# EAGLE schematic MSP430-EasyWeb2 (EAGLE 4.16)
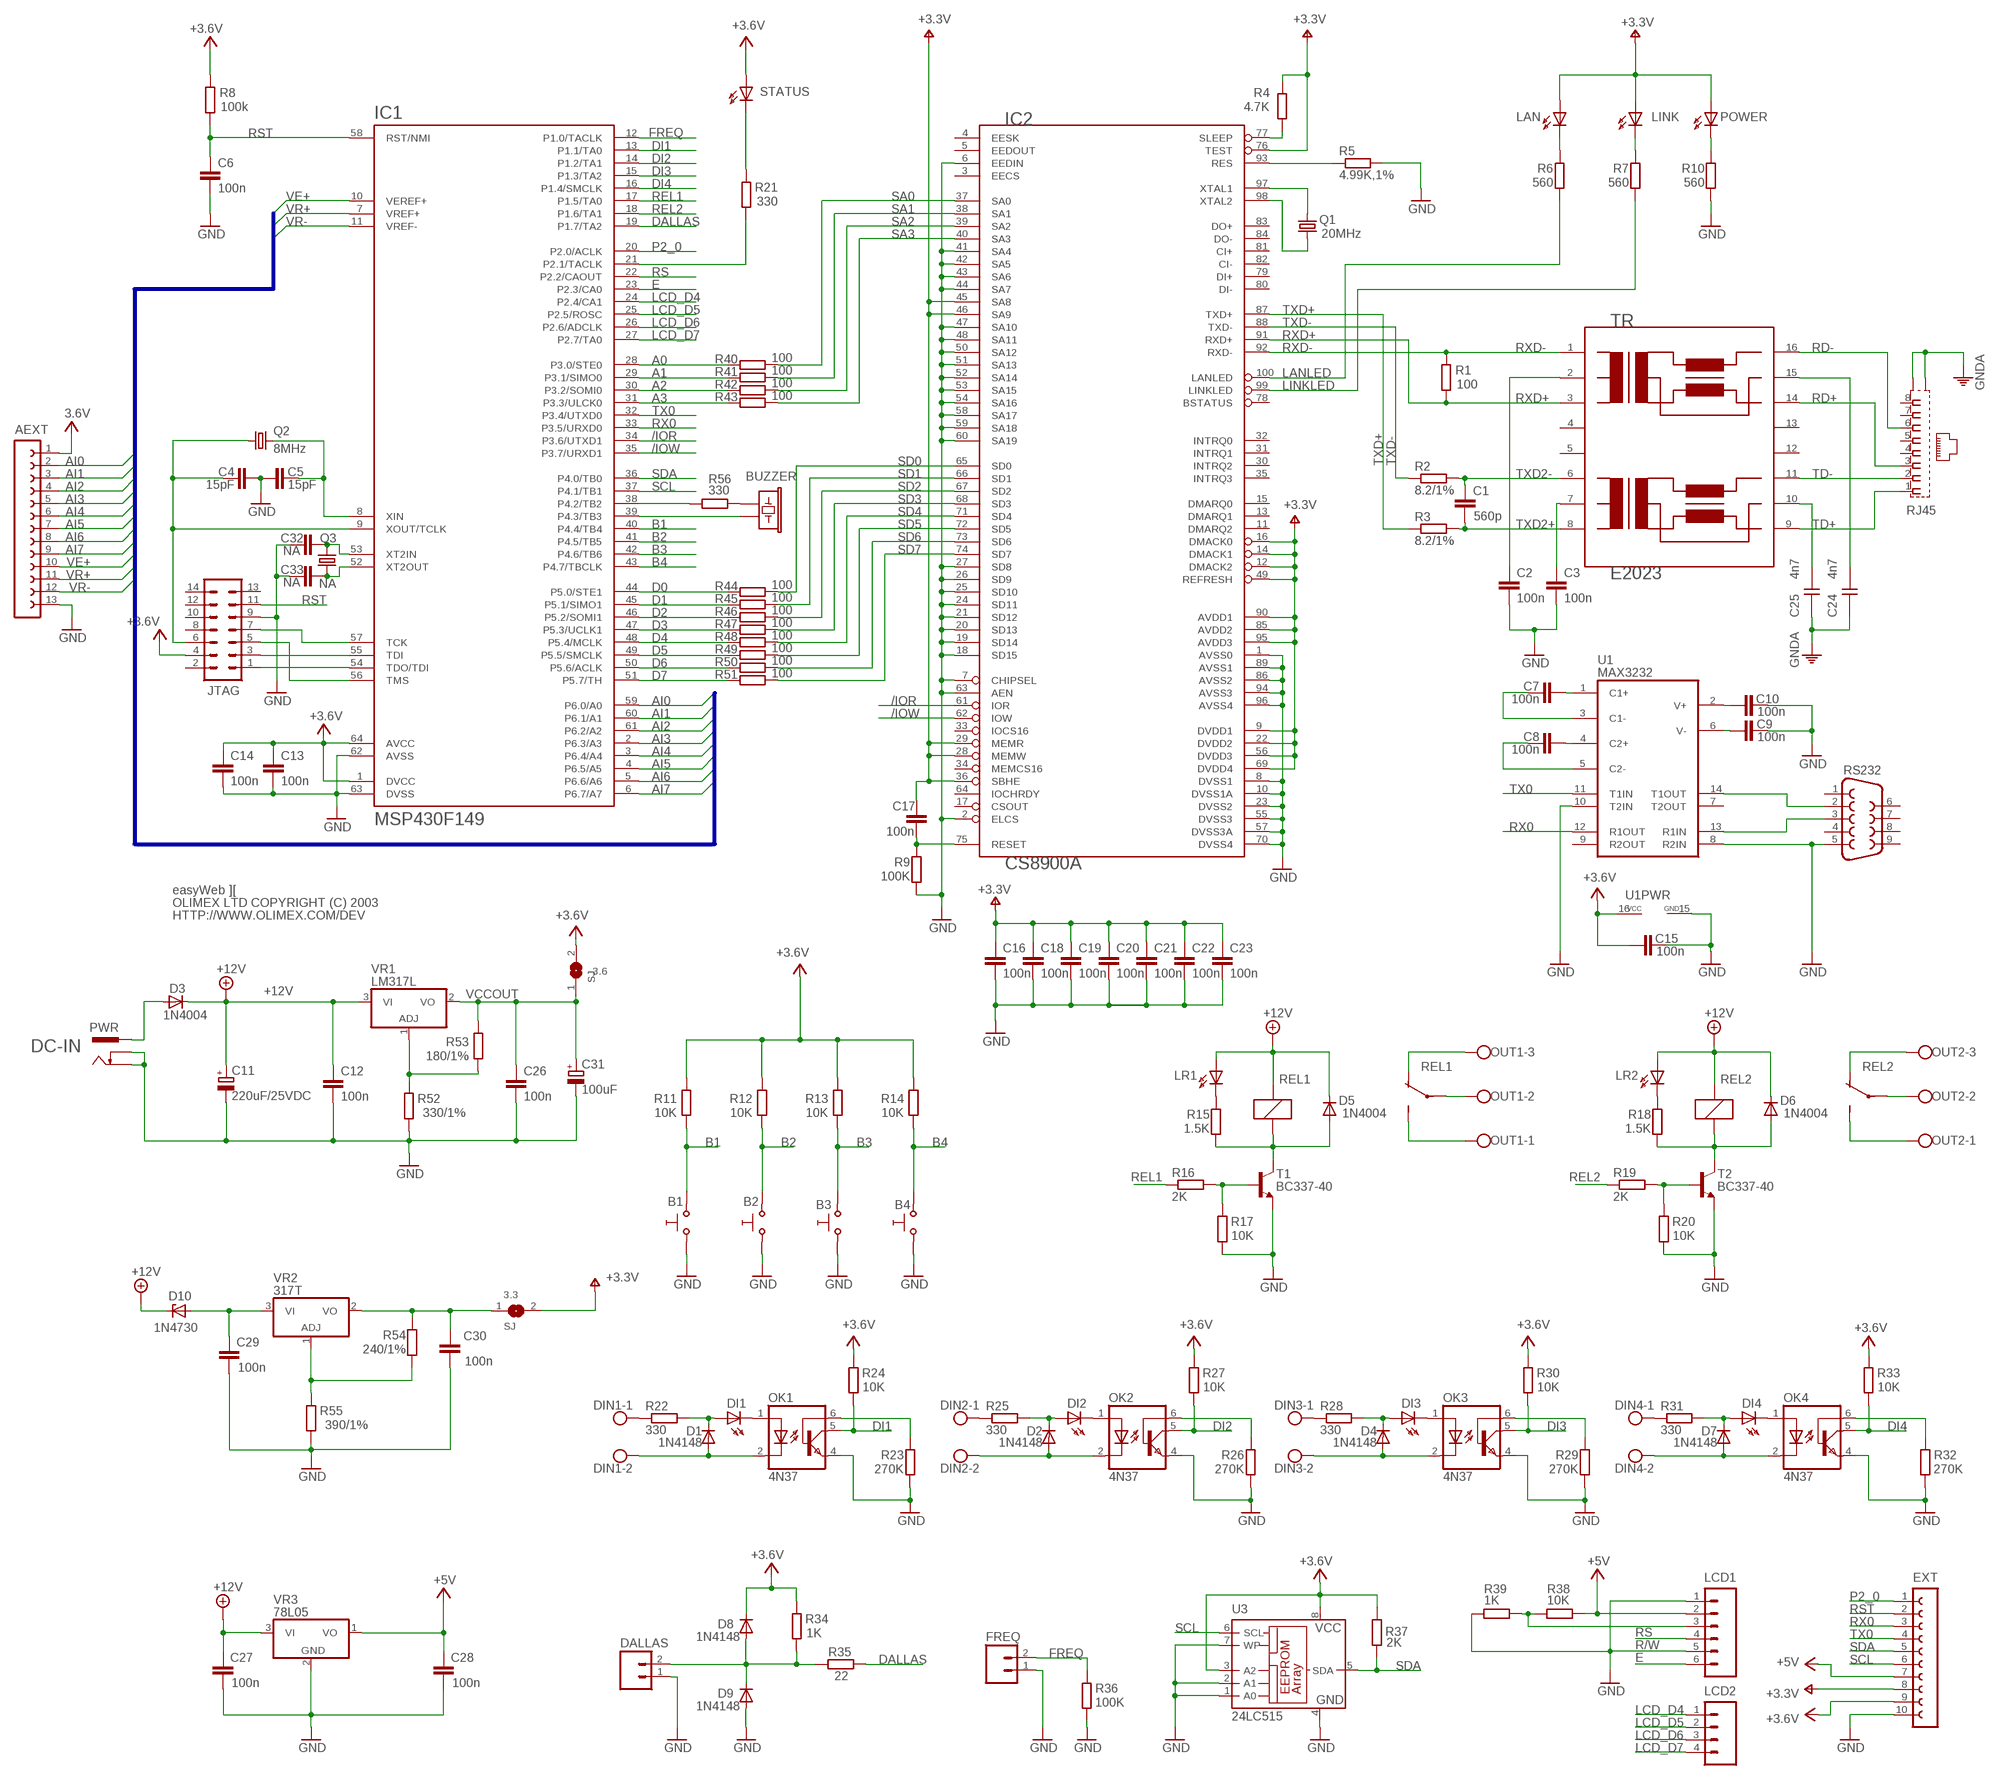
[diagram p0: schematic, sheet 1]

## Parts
3.3  SJ  [SJ]
3.6  SJ  [SJ]
AEXT  FE13-1  [FE13]
B1  SW-TAKT5  [SW_TAKT12X12]
B2  SW-TAKT5  [SW_TAKT12X12]
B3  SW-TAKT5  [SW_TAKT12X12]
B4  SW-TAKT5  [SW_TAKT12X12]
BUZZER  BUZ1  [BUZ1]
C1  560p  C-EUC0805  [C0805]
C2  100n  C-EUC0805  [C0805]
C3  100n  C-EUC0805  [C0805]
C4  15pF  C-EUC0805  [C0805]
C5  15pF  C-EUC0805  [C0805]
C6  100n  C-EUC0805  [C0805]
C7  100n  C-EUC0805  [C0805]
C8  100n  C-EUC0805  [C0805]
C9  100n  C-EUC0805  [C0805]
C10  100n  C-EUC0805  [C0805]
C11  220uF/25VDC  CPOL-EUE3.5-8  [E3,5-8]
C12  100n  C-EUC0805  [C0805]
C13  100n  C-EUC0805  [C0805]
C14  100n  C-EUC0805  [C0805]
C15  100n  C-EUC0805  [C0805]
C16  100n  C-EUC0805  [C0805]
C17  100n  C-EUC0805  [C0805]
C18  100n  C-EUC0805  [C0805]
C19  100n  C-EUC0805  [C0805]
C20  100n  C-EUC0805  [C0805]
C21  100n  C-EUC0805  [C0805]
C22  100n  C-EUC0805  [C0805]
C23  100n  C-EUC0805  [C0805]
C24  4n7  CAPNP-2,5@2  [C-5]
C25  4n7  CAPNP-2,5@2  [C-5]
C26  100n  C-EUC0805  [C0805]
C27  100n  C-EUC0805  [C0805]
C28  100n  C-EUC0805  [C0805]
C29  100n  C-EUC0805  [C0805]
C30  100n  C-EUC0805  [C0805]
C31  100uF  CPOL-EUE2.5-6  [E2,5-6]
C32  NA  C-EUC0805  [C0805]
C33  NA  C-EUC0805  [C0805]
D1  1N4148  DIODE-SOD80C  [SOD80C]
D2  1N4148  DIODE-SOD80C  [SOD80C]
D3  1N4004  DIODE-D-7.5  [D-7.5]
D4  1N4148  DIODE-SOD80C  [SOD80C]
D5  1N4004  D1N4004-7.62MM  [DO41-10]
D6  1N4004  D1N4004-7.62MM  [DO41-10]
D7  1N4148  DIODE-SOD80C  [SOD80C]
D8  1N4148  D1N4148-7.62MM  [DO35-10]
D9  1N4148  D1N4148-7.62MM  [DO35-10]
D10  1N4730  Z  [1N4742]
DALLAS  CON2PV2-2.54MM  [CON2.54MM-2-0]
DI1  LED5.0MM  [LED-5.0MM]
DI2  LED5.0MM  [LED-5.0MM]
DI3  LED5.0MM  [LED-5.0MM]
DI4  LED5.0MM  [LED-5.0MM]
DIN1  W237-102  [W237-102]
DIN2  W237-102  [W237-102]
DIN3  W237-102  [W237-102]
DIN4  W237-102  [W237-102]
EXT  FE10-1  [FE10]
FREQ  CON2PV2-2.54MM  [CON2.54MM-2-0]
IC1  MSP430F149  430F149  [S-PQFP-G]
IC2  CS8900A  [100LTQFP]
JTAG  ML14  [ML14]
LAN  LED5.0MM  [LED-5.0MM]
LCD1  HEAD6  [HEADER2.54-6-0]
LCD2  HEAD4  [HEADER2.54-4-0]
LINK  LED5.0MM  [LED-5.0MM]
LR1  LED5.0MM  [LED-5.0MM]
LR2  LED5.0MM  [LED-5.0MM]
OK1  4N37  [DIL06]
OK2  4N37  [DIL06]
OK3  4N37  [DIL06]
OK4  4N37  [DIL06]
OUT1  W237-103  [W237-103]
OUT2  W237-103  [W237-103]
POWER  LED5.0MM  [LED-5.0MM]
PWR  PWR-JAK2  [PWR-JACK2]
Q1  20MHz  HC49/S  [HC49/S]
Q2  8MHz  HC49/S  [HC49/S]
Q3  NA  HC49/S  [HC49/S]
R1  100  R-EU_R0805  [R0805]
R2  8.2/1%  R-EU_R0805  [R0805]
R3  8.2/1%  R-EU_R0805  [R0805]
R4  4.7K  R-EU_R0805  [R0805]
R5  4.99K,1%  R-EU_R0805  [R0805]
R6  560  R-EU_R0805  [R0805]
R7  560  R-EU_R0805  [R0805]
R8  100k  R-EU_R0805  [R0805]
R9  100K  R-EU_R0805  [R0805]
R10  560  R-EU_R0805  [R0805]
R11  10K  R-EU_R0805  [R0805]
R12  10K  R-EU_R0805  [R0805]
R13  10K  R-EU_R0805  [R0805]
R14  10K  R-EU_R0805  [R0805]
R15  1.5K  R-EU_R0805  [R0805]
R16  2K  R-EU_R0805  [R0805]
R17  10K  R-EU_R0805  [R0805]
R18  1.5K  R-EU_R0805  [R0805]
R19  2K  R-EU_R0805  [R0805]
R20  10K  R-EU_R0805  [R0805]
R21  330  R-EU_R0805  [R0805]
R22  330  R-EU_R0805  [R0805]
R23  270K  R-EU_R0805  [R0805]
R24  10K  R-EU_R0805  [R0805]
R25  330  R-EU_R0805  [R0805]
R26  270K  R-EU_R0805  [R0805]
R27  10K  R-EU_R0805  [R0805]
R28  330  R-EU_R0805  [R0805]
R29  270K  R-EU_R0805  [R0805]
R30  10K  R-EU_R0805  [R0805]
R31  330  R-EU_R0805  [R0805]
R32  270K  R-EU_R0805  [R0805]
R33  10K  R-EU_R0805  [R0805]
R34  1K  R-EU_R0805  [R0805]
R35  22  R-EU_R0805  [R0805]
R36  100K  R-EU_R0805  [R0805]
R37  2K  R-EU_R0805  [R0805]
R38  10K  R-EU_R0805  [R0805]
R39  1K  R-EU_R0805  [R0805]
R40  100  R-EU_R0805  [R0805]
R41  100  R-EU_R0805  [R0805]
R42  100  R-EU_R0805  [R0805]
R43  100  R-EU_R0805  [R0805]
R44  100  R-EU_R0805  [R0805]
R45  100  R-EU_R0805  [R0805]
R46  100  R-EU_R0805  [R0805]
R47  100  R-EU_R0805  [R0805]
R48  100  R-EU_R0805  [R0805]
R49  100  R-EU_R0805  [R0805]
R50  100  R-EU_R0805  [R0805]
R51  100  R-EU_R0805  [R0805]
R52  330/1%  R-EU_R0805  [R0805]
R53  180/1%  R-EU_R0805  [R0805]
R54  240/1%  R-EU_R0805  [R0805]
R55  390/1%  R-EU_R0805  [R0805]
R56  330  R-EU_R0805  [R0805]
REL1  RELAYH200F  [H200-FAT]
REL2  RELAYH200F  [H200-FAT]
RJ45  555153-1  [555153-1]
RS232  F09HP  [F09HP]
STATUS  LED5.0MM  [LED-5.0MM]
T1  BC337-40  NPNBC337-  [TO92-M]
T2  BC337-40  NPNBC337-  [TO92-M]
TR  E2023  [SO-16L]
U1  MAX3232  [SO16-150MILS]
U3  24LC515  24LCXX  [SO-08MN]
VR1  LM317L  LM317LZ  [TO92]
VR2  317T  [TO220H]
VR3  78L05  78L05Z  [TO92]

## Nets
317_+3.3V: 3.3.1 C30.2 R54.2 VR2.2(VO)
+3.3V [PWR]: 3.3.2 C16.1 C17.1 C18.1 C19.1 C20.1 C21.1 C22.1 C23.1 EXT.8 IC2.9(DVDD1) IC2.12(DMACK2) IC2.14(DMACK1) IC2.16(DMACK0) IC2.22(DVDD2) IC2.28(MEMW) IC2.29(MEMR) IC2.36(SBHE) IC2.45(SA8) IC2.46(SA9) IC2.49(REFRESH) IC2.56(DVDD3) IC2.69(DVDD4) IC2.76(TEST) IC2.85(AVDD2) IC2.90(AVDD1) IC2.95(AVDD3) LAN.A LINK.A POWER.A R4.2
+3.6V [PWR]: 3.6.2 AEXT.1 C13.1 C14.1 C15.1 D8.K EXT.9 IC1.1(DVCC) IC1.64(AVCC) JTAG.4 R8.2 R11.2 R12.2 R13.2 R14.2 R24.2 R27.2 R30.2 R33.2 R34.2 R37.2 STATUS.A U1.16(VCC) U3.3(A2) U3.8(VCC) ; supply symbol labelled 3.6V
+5V: C28.2 EXT.7 LCD1.2 R38.2 VR3.1(VO)
+12V [PWR]: C11.+ C12.1 C27.2 D3.C D5.K D6.K D10.K LR1.A LR2.A REL1.1 REL2.1 VR1.3(VI) VR3.3(VI)
/IOR: IC1.34(P3.6/UTXD1) IC2.61(IOR)
/IOW: IC1.35(P3.7/URXD1) IC2.62(IOW)
A0: IC1.28(P3.0/STE0) R40.1
A1: IC1.29(P3.1/SIMO0) R41.1
A2: IC1.30(P3.2/SOMI0) R42.1
A3: IC1.31(P3.3/ULCK0) R43.1
AI0: AEXT.2 IC1.59(P6.0/A0)
AI1: AEXT.3 IC1.60(P6.1/A1)
AI2: AEXT.4 IC1.61(P6.2/A2)
AI3: AEXT.5 IC1.2(P6.3/A3)
AI4: AEXT.6 IC1.3(P6.4/A4)
AI5: AEXT.7 IC1.4(P6.5/A5)
AI6: AEXT.8 IC1.5(P6.6/A6)
AI7: AEXT.9 IC1.6(P6.7/A7)
B1: B1.P$2 IC1.40(P4.4/TB4) R11.1
B2: B2.P$2 IC1.41(P4.5/TB5) R12.1
B3: B3.P$2 IC1.42(P4.6/TB6) R13.1
B4: B4.P$2 IC1.43(P4.7/TBCLK) R14.1
D0: IC1.44(P5.0/STE1) R44.1
D1: IC1.45(P5.1/SIMO1) R45.1
D2: IC1.46(P5.2/SOMI1) R46.1
D3: IC1.47(P5.3/UCLK1) R47.1
D4: IC1.48(P5.4/MCLK) R48.1
D5: IC1.49(P5.5/SMCLK) R49.1
D6: IC1.50(P5.6/ACLK) R50.1
D7: IC1.51(P5.7/TH) R51.1
DALLAS: IC1.19(P1.7/TA2) R35.2
DI1: IC1.13(P1.1/TA0) OK1.5(COL) R24.1
DI2: IC1.14(P1.2/TA1) OK2.5(COL) R27.1
DI3: IC1.15(P1.3/TA2) OK3.5(COL) R30.1
DI4: IC1.16(P1.4/SMCLK) OK4.5(COL) R33.1
E: IC1.23(P2.3/CA0) LCD1.6
ETH_RES: C17.2 IC2.75(RESET) R9.2
FREQ: FREQ.2 IC1.12(P1.0/TACLK) R36.2
GND [PWR]: AEXT.13 B1.P$1 B2.P$1 B3.P$1 B4.P$1 C2.2 C3.2 C4.2 C5.1 C6.2 C9.2 C10.2 C11.- C12.2 C13.2 C14.2 C15.2 C16.2 C18.2 C19.2 C20.2 C21.2 C22.2 C23.2 C26.2 C27.1 C28.1 C29.1 C30.1 C31.- C32.1 C33.1 D9.A DALLAS.1 EXT.10 FREQ.1 IC1.62(AVSS) IC1.63(DVSS) IC2.1(AVSS0) IC2.2(ELCS) IC2.6(EEDIN) IC2.7(CHIPSEL) IC2.8(DVSS1) IC2.10(DVSS1A) IC2.18(SD15) IC2.19(SD14) IC2.20(SD13) IC2.21(SD12) IC2.23(DVSS2) IC2.24(SD11) IC2.25(SD10) IC2.26(SD9) IC2.27(SD8) IC2.41(SA4) IC2.42(SA5) IC2.43(SA6) IC2.44(SA7) IC2.47(SA10) IC2.48(SA11) IC2.50(SA12) IC2.51(SA13) IC2.52(SA14) IC2.53(SA15) IC2.54(SA16) IC2.55(DVSS3) IC2.57(DVSS3A) IC2.58(SA17) IC2.59(SA18) IC2.60(SA19) IC2.63(AEN) IC2.70(DVSS4) IC2.86(AVSS2) IC2.89(AVSS1) IC2.94(AVSS3) IC2.96(AVSS4) JTAG.9 LCD1.1 LCD1.5 OK1.4(EMI) OK2.4(EMI) OK3.4(EMI) OK4.4(EMI) PWR.- PWR.-- R5.2 R9.1 R10.1 R17.1 R20.1 R23.1 R26.1 R29.1 R32.1 R36.1 R39.1 R52.1 R55.1 RS232.5 T1.1(E) T2.1(E) U1.8(R2IN) U1.10(T2IN) U1.15(GND) U3.1(A0) U3.2(A1) U3.4(GND) U3.7(WP) VR3.2(GND)
GNDA: C24.1 C25.1 RJ45.G1(S1) RJ45.G2(S2)
LANLED: IC2.100(LANLED) R6.1
LCD_D4: IC1.24(P2.4/CA1) LCD2.1
LCD_D5: IC1.25(P2.5/ROSC) LCD2.2
LCD_D6: IC1.26(P2.6/ADCLK) LCD2.3
LCD_D7: IC1.27(P2.7/TA0) LCD2.4
LINKLED: IC2.99(LINKLED) R7.1
N$1: POWER.K(C) R10.2
N$2: LINK.K(C) R7.2
N$3: LAN.K(C) R6.2
N$4: D3.A PWR.+
N$5: C7.2 U1.1(C1+)
N$6: C8.2 U1.4(C2+)
N$7: C2.1 TR.2
N$8: C3.1 TR.7
N$9: IC2.97(XTAL1) Q1.2
N$10: IC2.77(SLEEP) R4.1
N$11: IC2.93(RES) R5.1
N$12: IC2.98(XTAL2) Q1.1
N$13: C29.2 D10.A VR2.3(VI)
N$14: C9.1 U1.6(V-)
N$15: RS232.3 U1.13(R1IN)
N$16: C10.1 U1.2(V+)
N$17: D5.A R15.1 REL1.2 T1.3(C)
N$18: R16.2 R17.2 T1.2(B)
N$19: R21.2 STATUS.K(C)
N$20: DIN1.1 R22.1
N$21: C7.1 U1.3(C1-)
N$22: LR1.K(C) R15.2
N$23: C8.1 U1.5(C2-)
N$24: D1.A DIN1.2 OK1.2(C)
N$25: OUT1.3 REL1.O(CONTACTS:O)
N$26: C25.2 TR.10
N$27: OUT1.2 REL1.P(CONTACTS:P)
N$28: RS232.2 U1.14(T1OUT)
N$29: OUT1.1 REL1.S(CONTACTS:S)
N$30: C24.2 TR.15
N$31: D6.A R18.1 REL2.2 T2.3(C)
N$32: LR2.K(C) R18.2
N$33: R19.2 R20.2 T2.2(B)
N$34: DI1.K(C) OK1.1(A)
N$35: OUT2.3 REL2.O(CONTACTS:O)
N$36: OUT2.2 REL2.P(CONTACTS:P)
N$37: OUT2.1 REL2.S(CONTACTS:S)
N$38: D1.C DI1.A R22.2
N$39: OK1.6(BAS) R23.2
N$40: D8.A D9.K DALLAS.2 R34.1 R35.1
N$41: C32.2 IC1.53(XT2IN) Q3.2
N$42: DIN2.1 R25.1
N$43: D2.A DIN2.2 OK2.2(C)
N$44: DI2.K(C) OK2.1(A)
N$45: D2.C DI2.A R25.2
N$46: OK2.6(BAS) R26.2
N$47: R52.2 R53.1 VR1.1(ADJ)
N$48: DIN3.1 R28.1
N$49: D4.A DIN3.2 OK3.2(C)
N$50: DI3.K(C) OK3.1(A)
N$51: D4.C DI3.A R28.2
N$52: OK3.6(BAS) R29.2
N$53: LCD1.3 R38.1 R39.2
N$54: DIN4.1 R31.1
N$55: D7.A DIN4.2 OK4.2(C)
N$56: DI4.K(C) OK4.1(A)
N$57: D7.C DI4.A R31.2
N$58: OK4.6(BAS) R32.2
N$60: R54.1 R55.2 VR2.1(ADJ)
N$61: C33.2 IC1.52(XT2OUT) Q3.1
N$62: IC1.38(P4.2/TB2) R56.1
N$63: BUZZER.+ R56.2
P2_0: EXT.1 IC1.20(P2.0/ACLK)
P2_1: IC1.21(P2.1/TACLK) R21.1
P4_3: BUZZER.- IC1.39(P4.3/TB3)
RD+: RJ45.3 TR.14
RD-: RJ45.6 TR.16
REL1: IC1.17(P1.5/TA0) R16.1
REL2: IC1.18(P1.6/TA1) R19.1
RS: IC1.22(P2.2/CAOUT) LCD1.4
RST: C6.1 EXT.2 IC1.58(RST/NMI) JTAG.11 R8.1
RX0: EXT.3 IC1.33(P3.5/URXD0) U1.12(R1OUT)
RXD+: IC2.91(RXD+) R1.1 TR.3
RXD-: IC2.92(RXD-) R1.2 TR.1
SA0: IC2.37(SA0) R40.2
SA1: IC2.38(SA1) R41.2
SA2: IC2.39(SA2) R42.2
SA3: IC2.40(SA3) R43.2
SCL: EXT.6 IC1.37(P4.1/TB1) U3.6(SCL)
SD0: IC2.65(SD0) R44.2
SD1: IC2.66(SD1) R45.2
SD2: IC2.67(SD2) R46.2
SD3: IC2.68(SD3) R47.2
SD4: IC2.71(SD4) R48.2
SD5: IC2.72(SD5) R49.2
SD6: IC2.73(SD6) R50.2
SD7: IC2.74(SD7) R51.2
SDA: EXT.5 IC1.36(P4.0/TB0) R37.1 U3.5(SDA)
TCK: IC1.57(TCK) JTAG.7
TD+: RJ45.1 TR.9
TD-: RJ45.2 TR.11
TDI: IC1.55(TDI) JTAG.3
TDO/TDI: IC1.54(TDO/TDI) JTAG.1
TMS: IC1.56(TMS) JTAG.5
TX0: EXT.4 IC1.32(P3.4/UTXD0) U1.11(T1IN)
TXD2+: C1.1 R3.2 TR.8
TXD2-: C1.2 R2.2 TR.6
TXD+: IC2.87(TXD+) R3.1
TXD-: IC2.88(TXD-) R2.1
VCCOUT: 3.6.1 C26.1 C31.+ R53.2 VR1.2(VO)
VE+: AEXT.10 IC1.10(VEREF+)
VR+: AEXT.11 IC1.7(VREF+)
VR-: AEXT.12 IC1.11(VREF-)
XIN: C5.2 IC1.8(XIN) Q2.2
XOUT: C4.1 IC1.9(XOUT/TCLK) JTAG.6 Q2.1
Unconnected: IC2.3(EECS) IC2.4(EESK) IC2.5(EEDOUT) IC2.11(DMARQ2) IC2.13(DMARQ1) IC2.15(DMARQ0) IC2.17(CSOUT) IC2.30(INTRQ2) IC2.31(INTRQ1) IC2.32(INTRQ0) IC2.33(IOCS16) IC2.34(MEMCS16) IC2.35(INTRQ3) IC2.64(IOCHRDY) IC2.78(BSTATUS) IC2.79(DI+) IC2.80(DI-) IC2.81(CI+) IC2.82(CI-) IC2.83(DO+) IC2.84(DO-) JTAG.2 JTAG.8 JTAG.10 JTAG.12 JTAG.13 JTAG.14 RJ45.4 RJ45.5 RJ45.7 RJ45.8 RS232.1 RS232.4 RS232.6 RS232.7 RS232.8 RS232.9 TR.4 TR.5 TR.12 TR.13 U1.7(T2OUT) U1.9(R2OUT)

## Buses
VE+,VR+,VR-,AI[0..7]

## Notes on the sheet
- easyWeb ][
- OLIMEX LTD COPYRIGHT (C) 2003
- HTTP://WWW.OLIMEX.COM/DEV
- DC-IN
- R/W

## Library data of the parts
3.3 3.6 = JUMPER:SJ
AEXT = con-lsta:FE13-1: FEMALE HEADER
B1-B4 = gogo:SW-TAKT
BUZZER = gogo:BUZ
C1-C10 C12-C23 C26-C30 C32 C33 = rcl:C-EU: CAPACITOR, European symbol
C11 C31 = rcl:CPOL-EU: POLARIZED CAPACITOR, European symbol
C24 C25 = DISCRETE:CAPNP-2,5@2
D1-D4 D7 = diode:DIODE-: DIODE
D5 D6 D8 D9 = DOUBLE-SIDE:D: DIODES
D10 = DOUBLE-SIDE:Z: ZENER
DALLAS FREQ = DOUBLE-SIDE:CON2: CONNECTORS - 2 PINS
DI1-DI4 LAN LINK LR1 LR2 POWER STATUS = DOUBLE-SIDE:LED
DIN1-DIN4 = con-wago-500:W237-102: WAGO SCREW CLAMP
EXT = con-lsta:FE10-1: FEMALE HEADER
IC1 = easyWEB:430F149
IC2 = easyWEB:CS8900A
JTAG = con-harting-ml:ML14: HARTING
LCD1 = DOUBLE-SIDE:HEAD6
LCD2 = DOUBLE-SIDE:HEAD4
OK1-OK4 = optocoupler:4N37: MOTOROLA OPTO COUPLER
OUT1 OUT2 = con-wago-500:W237-103: WAGO SCREW CLAMP
PWR = gogo:PWR-JAK
Q1-Q3 = crystal:HC49/S: CRYSTAL
R1-R56 = rcl:R-EU_: RESISTOR, European symbol
REL1 REL2 = DOUBLE-SIDE:RELAY: RELAY
RJ45 = con-amp:555153-1: AMP CONNECTOR
RS232 = con-subd:F09: SUB-D
T1 T2 = DOUBLE-SIDE:NPN
TR = easyWEB:E2023
U1 = gogo:MAX3232
U3 = gogo:24LCXX
VR1 VR2 = linear:*317: Positive VOLTAGE REGULATOR
VR3 = linear:78*: Positive VOLTAGE REGULATOR

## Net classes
0 default: width 0.241 mm, drill 0.241 mm, clearance 0.61 mm
1 PWR: width 0.241 mm, drill 0.241 mm, clearance 0.61 mm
